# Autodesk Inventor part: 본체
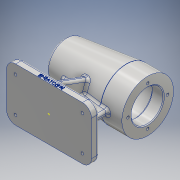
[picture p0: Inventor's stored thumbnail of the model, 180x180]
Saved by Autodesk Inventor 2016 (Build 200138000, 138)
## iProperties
Created: 2018-09
Part Number: 본체
Material: 알루미늄 6061
Document SubType Name: Modeling
Designer: CAMTIC
Density: 2.7 g/cm^3
Appearance: 알루미늄 - 평지
Author: CAMTIC
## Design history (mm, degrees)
sketch "스케치1"
  geometry: L1 (56, 35)-(-56, 35); L2 (-56, 35)-(-56, -35); L3 (-56, -35)-(56, -35); L4 (56, -35)-(56, 35); L5 (56, 35)-(-56, -35); L6 (-56, 35)-(56, -35); 1 further point
  constraints: 12 end point, 2 midpoint, 2 parallel, 1 horizontal, 1 perpendicular
  dimensions: "d0" = 112 distance of L2.end L3.end; "d1" = 70 distance of L1.end L2.end
extrude "돌출1" new body sketch "스케치1" distance "d2" = 10; taper "d3" = 0 deg
sketch "스케치2"
  geometry: L1 (0, 129.6)-(0, -21.6) reference; L2 (-105.225, 0)-(138.871, 0) reference; L3 (-70.354, 74)-(64.903, 74); L4 (-52.27, 98.144)-(28, 108); L5 (28, 108)-(56, 108); L6 (56, 108)-(56, 74); L7 (56, 74)-(-56, 74); L8 (104, 74)-(-56, 74); L9 (24, 74)-(-56, 74); A1 r 80 centre (24, 74) between (-52.27, 98.144) and (-56, 74); 1 further point
  constraints: 14 end point, 2 collinear, 2 horizontal, 2 perpendicular, 2 point on circle, 1 centre point
  dimensions: "d4" = 74 distance between parallel lines of L2 L3; "d5" = 28 distance from line of L4.end L6; "d6" = 34 distance of L5.end L6.end; "d7" = 7 deg angle of L4 L5; "d10" = 56 distance between parallel lines of L1 L6; "d13" = 112 distance of L7.end L6.end; "d14" = 80 radius of A1
revolve "회전1" sketch "스케치2" stored, may be unused: angle "d18" = 90 deg
sketch "스케치3"
  geometry: L1 (-52.27, 98.144)-(28, 108) reference; L2 (56, 40)-(56, 108) reference; L3 (28, 108)-(56, 108) reference; L4 (-52.27, 49.856)-(28, 40) reference; L5 (28, 40)-(56, 40) reference; L6 (0, 129.6)-(0, -21.6) reference; L7 (-78.4, 0)-(78.4, 0) reference; L8 (-85.36, 74)-(107.165, 74); L9 (-50, 74)-(-50, 84.5); L10 (-50, 84.5)-(-47, 84.5); L11 (-47, 84.5)-(-47, 90); L12 (-47, 90)-(-43, 90); L13 (-43, 90)-(-43, 91.5); L14 (-43, 91.5)-(-25, 91.5); L15 (-25, 91.5)-(-25, 95); L16 (-25, 95)-(-13, 95); L17 (-13, 95)-(-13, 98); L18 (-13, 98)-(41, 98); L19 (41, 98)-(41, 95); L20 (41, 95)-(56, 95); L21 (56, 95)-(56, 74); L22 (56, 74)-(-50, 74); A1 r 80 centre (24, 74) between (-52.27, 98.144) and (-52.27, 49.856) reference; 1 further point
  constraints: 30 end point, 13 perpendicular, 2 collinear, 1 horizontal, 1 vertical
  dimensions: "d19" = 74 distance between parallel lines of L7 L8; "d20" = 15 distance of L19.end L20.end; "d21" = 54 distance of L17.end L18.end; "d22" = 12 distance of L15.end L16.end; "d23" = 18 distance of L13.end L14.end; "d24" = 4 distance of L11.end L12.end; "d25" = 3 distance of L9.end L10.end; "d26" = 10.5 distance of L9.start L9.end; "d27" = 16 distance between parallel lines of L22 L12; "d28" = 17.5 distance between parallel lines of L22 L14; "d29" = 21 distance between parallel lines of L22 L16; "d30" = 24 distance between parallel lines of L8 L18; "d31" = 21 distance between parallel lines of L8 L20
revolve "회전2" sketch "스케치3" stored, may be unused: angle "d32" = 90 deg
fillet "모깎기1" dims "d33" = 0.3
fillet "모깎기2" dims "d34" = 3
chamfer "모따기1" distance "d35" = 1; stored, may be unused: second distance "d36" = 2, angle "d37" = 45 deg
fillet "모깎기3" dims "d38" = 3
fillet "모깎기4" dims "d39" = 3
sketch "스케치4"
  geometry: L1 (-50.331, 49.618)-(27.818, 40.022) reference; L2 (-56, 10)-(56, 10) reference; L3 (-50.331, 49.618)-(27.818, 40.022) reference; L4 (28.183, 40)-(56, 40) reference; L5 (0, 129.6)-(0, -21.6) reference; L6 (-78.4, 0)-(78.4, 0) reference; L7 (-38, 10)-(-27.899, 47.699); L8 (-27.899, 47.699)-(38, 47.699); L9 (38, 47.699)-(38, 10); L10 (38, 10)-(-38, 10); L11 (-56, 0)-(-56, 10) reference; L12 (56, 0)-(56, 10) reference; A1 r 3 centre (28.183, 43) between (27.818, 40.022) and (28.183, 40) reference; 1 further point
  constraints: 8 end point, 1 collinear, 1 horizontal, 1 parallel, 1 vertical
  dimensions: "d40" = 18 distance from line of L7.start L11; "d41" = 18 distance from line of L9.end L12; "d42" = 105 deg angle of L2 L7; "d43" = 37.69876 distance between parallel lines of L10 L8
extrude "돌출2" join sketch "스케치4" stored distance "d44" = 8; taper "d45" = 0 deg
sketch "스케치6" dims "d51" = 52
  geometry: C1 r 34 at (0, 0) reference; C2 r 17.5 at (0, 0) reference; 3 further points
  constraints: 1 coincident, 1 vertical alignment, 2 other
hole "구멍1" sketch "스케치6" at (0, 26) diameter "d52" = 3.459; stored, may be unused: countersink angle "d56" = 90 deg, drill point angle "d58" = 118 deg; dims "d53" = 8, "d54" = 4, "d55" = 2, "d57" = 11
fillet "모깎기5" dims "d62" = 12
hole "구멍2" diameter "d65" = 3.459; stored, may be unused: countersink angle "d69" = 90 deg, drill point angle "d71" = 118 deg; dims "d63" = 10, "d64" = 10, "d66" = 5.5, "d67" = 9.5, "d68" = 5.4, "d70" = 11
fillet "모깎기9" dims "d92" = 3
sketch "스케치12"
  geometry: L1 (10, -23)-(10, 23) reference; L2 (7, 35)-(0, 35) reference; L3 (0, -35)-(7, -35) reference; L4 (55.214, 15.543)-(10, 32); L5 (10, 32)-(10, -32); L6 (10, -32)-(55.596, -15.404); C1 r 34 at (74, 0) reference; A1 r 24.382 centre (74, 0) between (55.214, 15.543) and (55.214, -15.543); 5 further points
  constraints: 6 end point, 3 point on line, 2 point on circle, 1 centre point, 1 coincident, 1 collinear, 1 vertical, 4 other
  dimensions: "d93" = 20 deg angle of L4 L2; "d94" = 20 deg angle of L3 L6
extrude "돌출6" join sketch "스케치12" stored distance "d95" = 8; taper "d96" = 0 deg
fillet "모깎기10" dims "d97" = 3
fillet "모깎기11" dims "d98" = 3
fillet "모깎기12" dims "d99" = 3
fillet "모깎기13" dims "d100" = 3
fillet "모깎기14" dims "d101" = 3
fillet "모깎기15" dims "d102" = 3
sketch "스케치13"
  geometry: L1 (26.916, 5.389)-(61.084, 5.389); L2 (61.084, 5.389)-(61.084, 0.611); L3 (61.084, 0.611)-(26.916, 0.611); L4 (26.916, 0.611)-(26.916, 5.389); L5 (44, 5.389)-(44, 0.611); L6 (26.916, 3)-(61.084, 3); L7 (0, 0)-(88, 0) reference; L8 (100, 0)-(100, 7) reference; 1 further point
  constraints: 4 end point, 4 midpoint, 2 other
  dimensions: "d103" = 3 distance between parallel lines of L6 L7; "d104" = 56 distance from line of L5.start L8
feature "엠보싱1" sketch "스케치13" dims "d0" = 112, "d1" = 70, "d105" = 0.5, "d106" = 0
node "솔리드1"
pattern_circular "원형 패턴1" dims angle "d60" = 360 deg
mirror "대칭1"
mirror "대칭2"
